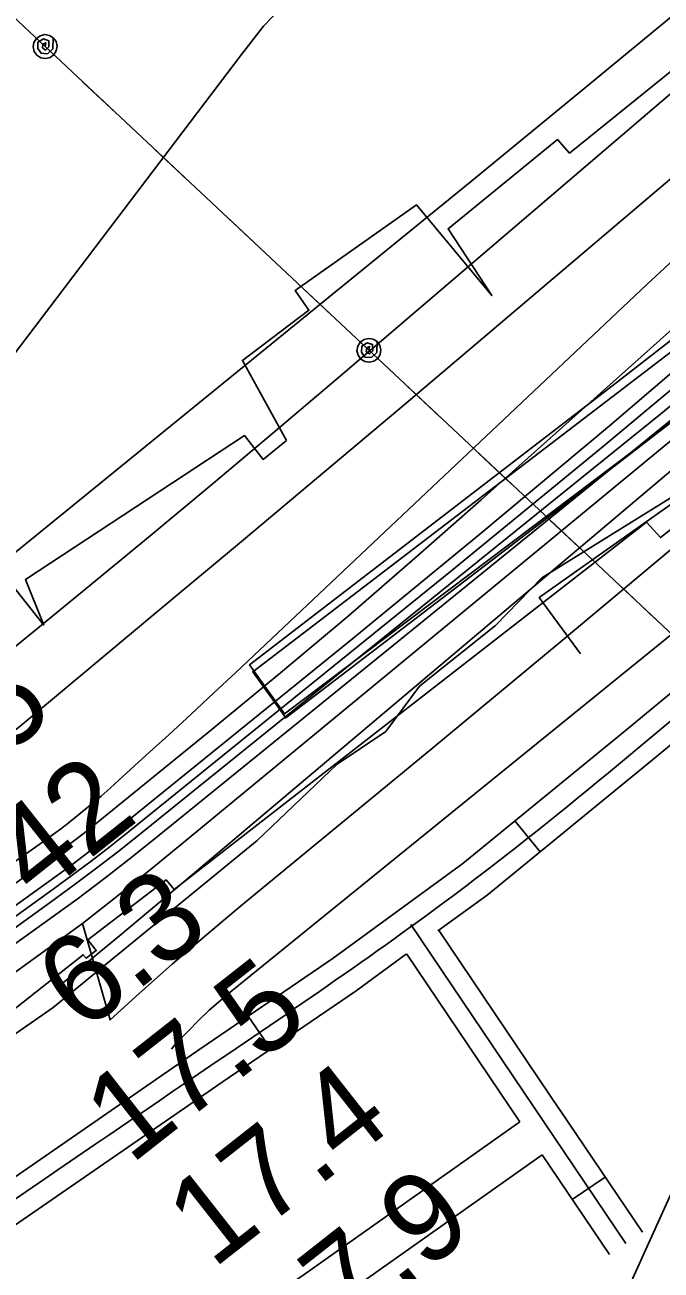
# Model space of a CAD drawing. Extents: x 3625074 to 3663148, y 511451 to 537151.
# Drawn here: x 3645581 to 3646060, y 521187 to 522124 of the extents above; entities that cross this region are included whole.
import ezdxf

# ---------------------------------------------------------------- set-up
doc = ezdxf.new("R2010")
doc.units = 0
for name, color, linetype in [('V-CHAN-DOCK', 7, 'Continuous'), ('V-LEVE-TOET', 7, 'Continuous'), ('V-RIVR-EDGE', 7, 'Continuous'), ('V-RIVR-RANG', 7, 'Continuous'), ('V-ROAD-CNTR', 7, 'Continuous'), ('V-RRAP-FSHR', 7, 'Continuous'), ('V-RRAP-RVMT', 7, 'Continuous'), ('V-TOPO-DPTH', 7, 'Continuous'), ('V-TOPO-MAJR', 7, 'Continuous'), ('V-TOPO-MINR', 7, 'Continuous'), ('V-TOPO-WATR', 7, 'Continuous'), ('V-UTIL-LINE', 7, 'Continuous')]:
    doc.layers.add(name, color=color, linetype=linetype)

msp = doc.modelspace()

# ---------------------------------------------------------------- linework, layer by layer
at = {"layer": 'V-CHAN-DOCK'}
msp.add_lwpolyline([(3647077.96, 522756.05), (3646494.93, 522231.96), (3646126.12, 521923.52), (3645752.62, 521637.55), (3645777.4, 521602.85), (3645987.62, 521763.73), (3646113.04, 521860.5), (3646144.11, 521817.9), (3646502.26, 522109.41), (3646582.43, 522257.46), (3646607.69, 522282.25), (3646709.59, 522172.98), (3646718.27, 522179.67), (3646642.33, 522262.11), (3646648.42, 522267.73), (3646654.37, 522261.27), (3646707.66, 522310.36), (3646678.61, 522341.89), (3646761.6, 522418.33), (3646806.4, 522369.7), (3646860.57, 522419.59), (3646817.55, 522466.3), (3646902.8, 522544.82)], dxfattribs=at)
at = {"layer": 'V-LEVE-TOET'}
msp.add_lwpolyline([(3646068.19, 521247.24), (3646026.38, 521154.84), (3645983.31, 521094.35), (3645844.66, 520999.75), (3645673.55, 520881.76), (3645536.38, 520786.62), (3645226.21, 520566.05), (3644923.09, 520354.77)], dxfattribs=at)
at = {"layer": 'V-RIVR-EDGE'}
msp.add_lwpolyline([(3644858.05, 520878.31), (3644968.08, 520945.88), (3645173.74, 521084.64), (3645302.43, 521176.18), (3645602.51, 521384.95), (3645755.9, 521510.64), (3645816.08, 521568.12), (3645852.76, 521592.64), (3645878.06, 521626.8), (3645935.2, 521672.28), (3645970.11, 521708.22), (3646075.93, 521773.99), (3646145.69, 521823.64), (3646116.97, 521862.74), (3645776.55, 521606.04), (3645750.23, 521642.72), (3646026.91, 521855.76), (3646319.23, 522083.16), (3646492.51, 522241.21), (3646750, 522464.5), (3646880.57, 522583.04)], dxfattribs=at)
at = {"layer": 'V-ROAD-CNTR'}
for p, q in [((3645968.72, 521502.17), (3645949.73, 521525.39)), ((3645766.08, 521353.73), (3645749.19, 521378.52)), ((3645992.89, 521240.58), (3646017.76, 521257.35))]:
    msp.add_line(p, q, dxfattribs=at)
for points in [[(3646202.23, 521733.05), (3646154.44, 521693.88), (3646032.61, 521593.13), (3645910.52, 521493.35), (3645812.98, 521421.98), (3645712.65, 521353.64), (3645559.67, 521247.79), (3645406.72, 521141.74), (3645302.19, 521066.22), (3645197.89, 520990.99), (3645080.09, 520911.17), (3644961.1, 520832.8), (3644862.35, 520768.83), (3644762.83, 520706.48), (3644752.66, 520700.73), (3644746.65, 520697.64)], [(3646209.85, 521700.51), (3646173.5, 521670.72), (3646051.66, 521569.96), (3645928.88, 521469.61), (3645891.9, 521442.55)], [(3646033.27, 521207.5), (3645871.52, 521447.45)], [(3645983.7, 521307.59), (3645892.8, 521442.72)], [(3645868.32, 521425.3), (3645830.29, 521397.48), (3645729.63, 521328.9), (3645576.75, 521223.12), (3645424.05, 521117.25), (3645319.75, 521041.9), (3645215.08, 520966.4), (3645096.76, 520886.22), (3644977.51, 520807.68), (3644918.88, 520769.71)], [(3645953.52, 521298.98), (3645868.47, 521425.13)], [(3646045.71, 521215.89), (3645983.6, 521308.03)], [(3645495.29, 520976.18), (3645636.38, 521076.89), (3645791.19, 521184.04), (3645953.52, 521298.98)], [(3645512.72, 520951.76), (3645653.63, 521052.35), (3645808.4, 521159.47), (3645970.29, 521274.1)], [(3646020.84, 521199.12), (3645970.29, 521274.1)]]:
    msp.add_lwpolyline(points, dxfattribs=at)
msp.add_spline([(3646385.44, 521861.38), (3646274.78, 521773.03), (3646163.97, 521682.3), (3645919.7, 521481.48), (3645721.14, 521341.27), (3645415.39, 521129.49), (3645206.49, 520978.7), (3644969.3, 520820.24), (3644770.51, 520693.59), (3644748.79, 520681.89)], degree=3, dxfattribs=at)
at = {"layer": 'V-RRAP-FSHR'}
msp.add_lwpolyline([(3645999.02, 521651.09), (3645968.08, 521693.34), (3646092.2, 521781.22), (3646140.44, 521816.06)], dxfattribs=at)
at = {"layer": 'V-RRAP-RVMT'}
for points in [[(3645778.05, 521811.6), (3645744.79, 521871.76), (3645794.83, 521909.61), (3645784.52, 521924.5), (3645875.64, 521988.83), (3645932.32, 521920.66), (3645899.45, 521970.94), (3645981.84, 522038.03), (3645990.85, 522027.65), (3646137.64, 522146.74), (3646162.19, 522118.42), (3646315.69, 522252.57), (3646307.62, 522263.78), (3646450.76, 522377.01)], [(3646566.5, 522236.25), (3646429.97, 522125.78), (3646446.91, 522104.74), (3646286.28, 521962.68), (3646270.34, 521979.94), (3646110.48, 521850.51), (3646127.66, 521829.57), (3646124.49, 521827.12), (3646142.29, 521802.96), (3646059.24, 521738.5), (3646048.7, 521750.21)], [(3646048.7, 521750.21), (3645693.48, 521473.65), (3645687.35, 521481.01), (3645628.52, 521435.89), (3645634.85, 521427.81), (3645627.27, 521422.06), (3645624.95, 521424.7), (3645481.09, 521311.15), (3645454.3, 521346.15), (3645455.47, 521347.06), (3645323.4, 521520.35), (3645397.29, 521586.01), (3645395.74, 521587.52), (3645557.37, 521720.5), (3645595.36, 521672.72), (3645581.65, 521707.11), (3645746.27, 521815.24), (3645760.37, 521797.4), (3645778.05, 521811.6)]]:
    msp.add_lwpolyline(points, dxfattribs=at)
at = {"layer": 'V-TOPO-DPTH'}
for points in [[(3647339.69, 522951.38), (3646608.99, 522302.38), (3646587.77, 522283.57), (3646566.54, 522264.78), (3646545.27, 522246.03), (3646523.98, 522227.3), (3646399.52, 522118), (3646315.54, 522045.16), (3646230.97, 521973.04), (3646145.5, 521901.98), (3646059.44, 521831.62), (3645668.58, 521516.15), (3645651.98, 521502.97), (3645635.25, 521489.97), (3645618.3, 521477.23), (3645601.23, 521464.68), (3644764.22, 520859.54)], [(3644764.22, 520859.54), (3645601.23, 521464.68), (3645618.3, 521477.23), (3645635.25, 521489.97), (3645651.98, 521502.97), (3645668.58, 521516.15), (3646059.44, 521831.62), (3646145.5, 521901.98), (3646230.97, 521973.04), (3646315.54, 522045.16), (3646399.52, 522118), (3646523.98, 522227.3), (3646545.27, 522246.03), (3646566.54, 522264.78), (3646587.77, 522283.57), (3646608.99, 522302.38), (3647339.69, 522951.38)], [(3644821.88, 520934.86), (3644923.65, 521001.72), (3645024.72, 521069.6), (3645124.75, 521139.02), (3645224.07, 521209.46), (3645603.76, 521483.12), (3645615.44, 521491.69), (3645627.02, 521500.38), (3645638.45, 521509.28), (3645649.78, 521518.3), (3645825.06, 521660.24), (3645923.42, 521740.98), (3646021.04, 521822.58), (3646117.58, 521905.46), (3646213.39, 521989.2), (3646494.37, 522238.11), (3646521.05, 522261.73), (3646547.73, 522285.35), (3646574.43, 522308.96), (3646601.13, 522332.56), (3646763.98, 522476.42)], [(3646763.98, 522476.42), (3646601.13, 522332.56), (3646574.43, 522308.96), (3646547.73, 522285.35), (3646521.05, 522261.73), (3646494.37, 522238.11), (3646213.39, 521989.2), (3646117.58, 521905.46), (3646021.04, 521822.58), (3645923.42, 521740.98), (3645825.06, 521660.24), (3645649.78, 521518.3), (3645638.45, 521509.28), (3645627.02, 521500.38), (3645615.44, 521491.69), (3645603.76, 521483.12), (3645224.07, 521209.46), (3645124.75, 521139.02), (3645024.72, 521069.6), (3644923.65, 521001.72), (3644821.88, 520934.86)], [(3646832.59, 522462.93), (3646750.1, 522390.1), (3646648.05, 522300.13), (3646616.52, 522272.37), (3646584.95, 522244.64), (3646553.33, 522216.97), (3646521.68, 522189.33), (3646520.78, 522188.54), (3646488.55, 522160.67), (3646456.16, 522132.98), (3646423.55, 522105.56), (3646390.78, 522078.32), (3645704.73, 521512.61), (3645678.17, 521490.91), (3645651.48, 521469.39), (3645624.6, 521448.11), (3644681.81, 520765.81)], [(3646832.59, 522462.93), (3646750.1, 522390.1), (3646648.05, 522300.13), (3646616.52, 522272.37), (3646584.95, 522244.64), (3646553.33, 522216.97), (3646521.68, 522189.33), (3646520.78, 522188.54), (3646488.55, 522160.67), (3646456.16, 522132.98), (3646423.55, 522105.56), (3646390.78, 522078.32), (3645704.73, 521512.61), (3645678.17, 521490.91), (3645651.48, 521469.39), (3645624.6, 521448.11)], [(3645624.6, 521448.11), (3645645.29, 521375.62), (3645667.16, 521395.52), (3645692.26, 521417.83), (3645717.74, 521439.71), (3645743.47, 521461.29), (3645886.55, 521579.19), (3645983.74, 521659.83), (3646080.56, 521740.9), (3646176.84, 521822.63), (3646272.75, 521904.78), (3646592.71, 522180.72), (3646606.83, 522192.98), (3646620.91, 522205.29), (3646634.9, 522217.7), (3646648.84, 522230.16), (3646893.45, 522450.21)], [(3645306.01, 521288.27), (3645384.77, 521343.08), (3645463.06, 521398.58), (3645606.32, 521501.53), (3645612.59, 521506.12), (3645618.8, 521510.79), (3645624.93, 521515.56), (3645631, 521520.4), (3645722.15, 521594.45), (3645773.45, 521636.73), (3645824.34, 521679.49), (3645874.61, 521722.98), (3645924.47, 521766.94), (3646511.67, 522292.19)], [(3646511.67, 522292.19), (3645924.47, 521766.94), (3645874.61, 521722.98), (3645824.34, 521679.49), (3645773.45, 521636.73), (3645722.15, 521594.45), (3645631, 521520.4), (3645624.93, 521515.56), (3645618.8, 521510.79), (3645612.59, 521506.12), (3645606.32, 521501.53), (3645463.06, 521398.58), (3645384.77, 521343.08), (3645306.01, 521288.27)], [(3644596.26, 520846.15), (3645548.55, 521477.78), (3645559.03, 521484.82), (3645569.45, 521491.92), (3645579.8, 521499.14), (3645590.1, 521506.44), (3645608.9, 521519.92), (3645611.43, 521521.82), (3645612.25, 521522.47), (3645624.61, 521532.52), (3645631.56, 521538.26), (3645638.44, 521544.08), (3645645.23, 521550.01), (3645651.95, 521556.03), (3645672.51, 521574.75), (3645689.42, 521590.23), (3645706.28, 521605.77), (3645723.05, 521621.39), (3645739.77, 521637.08), (3646049.11, 521928.91), (3646123.37, 521998.03), (3646198.23, 522066.46), (3646274.01, 522133.88)], [(3646274.01, 522133.88), (3646198.23, 522066.46), (3646123.37, 521998.03), (3646049.11, 521928.91), (3645739.77, 521637.08), (3645723.05, 521621.39), (3645706.28, 521605.77), (3645689.42, 521590.23), (3645672.51, 521574.75), (3645651.95, 521556.03), (3645645.23, 521550.01), (3645638.44, 521544.08), (3645631.56, 521538.26), (3645624.61, 521532.52), (3645612.25, 521522.47), (3645611.43, 521521.82), (3645608.9, 521519.92), (3645590.1, 521506.44), (3645579.8, 521499.14), (3645569.45, 521491.92), (3645559.03, 521484.82), (3645548.55, 521477.78), (3644596.26, 520846.15)]]:
    msp.add_lwpolyline(points, dxfattribs=at)
at = {"layer": 'V-TOPO-MAJR'}
msp.add_lwpolyline([(3644883.64, 521091.89), (3644988.39, 521166.06), (3645092.61, 521240.97), (3645196.48, 521316.37), (3645543.06, 521569.85), (3645552.21, 521576.68), (3645561.28, 521583.63), (3645570.22, 521590.74), (3645579.06, 521597.98), (3645684.26, 521685.66), (3645745.56, 521736.9), (3645806.78, 521788.25), (3645867.85, 521839.76), (3645928.84, 521891.39), (3646425.63, 522313.09), (3646452.95, 522336.12), (3646480.36, 522359.04), (3646507.92, 522381.79), (3646535.59, 522404.41), (3647111.04, 522871.97)], dxfattribs=at)
at = {"layer": 'V-TOPO-MINR'}
for points in [[(3644582.77, 520968.63), (3645480.34, 521651.95), (3645487.89, 521657.76), (3645495.4, 521663.62), (3645502.85, 521669.55), (3645510.27, 521675.52), (3645917.36, 522007.03), (3646001.6, 522076.11), (3646085.53, 522145.57), (3646169, 522215.58), (3646252.15, 522285.98), (3646390.26, 522403.7), (3646404.11, 522415.52), (3646417.96, 522427.36), (3646431.78, 522439.21), (3646445.6, 522451.07), (3647117.87, 523028.96)], [(3644595.24, 521097.76), (3645415.07, 521701.98), (3645431.19, 521714.11), (3645447.15, 521726.44), (3645462.86, 521739.09), (3645478.41, 521751.95), (3645744.23, 522102), (3645760.57, 522123.27), (3645779.49, 522142.89), (3646227.47, 522533.61), (3646253.63, 522556.06), (3646280.02, 522578.22), (3646306.77, 522599.95), (3646333.75, 522621.4), (3646754.89, 522950.68), (3646803.83, 522986.12), (3646854.28, 523019.03)], [(3645604.42, 521398.93), (3645610.57, 521404.14), (3645624.48, 521415.79), (3645638.43, 521427.38), (3645652.4, 521438.96), (3645666.34, 521450.57), (3645680.25, 521462.22), (3645694.13, 521473.91), (3646565.2, 522209.52), (3646570.07, 522213.65), (3646574.92, 522217.79), (3646579.76, 522221.95), (3646584.58, 522226.12), (3646589.4, 522230.31), (3646594.21, 522234.5), (3646599.01, 522238.71), (3646603.81, 522242.91), (3646617.18, 522254.65), (3646628.65, 522264.73), (3646640.12, 522274.82), (3646651.59, 522284.92), (3646663.05, 522295.03), (3647444.8, 522984.97)], [(3644764.22, 520859.54), (3645601.23, 521464.68), (3645618.3, 521477.23), (3645635.25, 521489.97), (3645651.98, 521502.97), (3645668.58, 521516.15), (3646059.44, 521831.62), (3646145.5, 521901.98), (3646230.97, 521973.04), (3646315.54, 522045.16), (3646399.52, 522118), (3646523.98, 522227.3), (3646545.27, 522246.03), (3646566.54, 522264.78), (3646587.77, 522283.57), (3646608.99, 522302.38), (3647339.69, 522951.38)], [(3644678.32, 520789.42), (3645620.56, 521466.43), (3645641.32, 521482.27), (3645661.86, 521498.4), (3645682.26, 521514.72), (3646222.14, 521952.8), (3646282.05, 522001.97), (3646341.58, 522051.57), (3646400.56, 522101.84), (3646459.17, 522152.54), (3646522.84, 522208.25), (3646549.31, 522231.46), (3646575.75, 522254.7), (3646602.15, 522277.98), (3646628.52, 522301.3), (3647118.2, 522735.2)], [(3644876.76, 520952.56), (3644938.09, 520995.06), (3644998.95, 521038.24), (3645602.49, 521473.9), (3645616.87, 521484.46), (3645631.13, 521495.18), (3645645.21, 521506.13), (3645659.18, 521517.23), (3645902.45, 521713.92), (3646013.64, 521804.99), (3646124.02, 521897.01), (3646233.21, 521990.45), (3646341.61, 522084.82), (3646525.1, 522246.66), (3646541.15, 522260.82), (3646557.2, 522274.99), (3646573.23, 522289.18), (3646589.26, 522303.37), (3647057.44, 522718.1)], [(3644821.88, 520934.86), (3644923.65, 521001.72), (3645024.72, 521069.6), (3645124.75, 521139.02), (3645224.07, 521209.46), (3645603.76, 521483.12), (3645615.44, 521491.69), (3645627.02, 521500.38), (3645638.45, 521509.28), (3645649.78, 521518.3), (3645825.06, 521660.24), (3645923.42, 521740.98), (3646021.04, 521822.58), (3646117.58, 521905.46), (3646213.39, 521989.2), (3646494.37, 522238.11), (3646521.05, 522261.73), (3646547.73, 522285.35), (3646574.43, 522308.96), (3646601.13, 522332.56), (3646763.98, 522476.42)], [(3645645.29, 521375.62), (3645667.16, 521395.52), (3645692.26, 521417.83), (3645717.74, 521439.71), (3645743.47, 521461.29), (3645886.55, 521579.19), (3645983.74, 521659.83), (3646080.56, 521740.9), (3646176.84, 521822.63), (3646272.75, 521904.78), (3646592.71, 522180.72), (3646606.83, 522192.98), (3646620.91, 522205.29), (3646634.9, 522217.7), (3646648.84, 522230.16), (3646893.45, 522450.21)], [(3645691.57, 521353.54), (3645693.99, 521356.88), (3645703.9, 521367.23), (3645711.78, 521375.17), (3645719.86, 521382.9), (3645728.22, 521390.31), (3645736.78, 521397.52), (3646344.81, 521890.45), (3646381.61, 521919.99), (3646418.6, 521949.28), (3646455.88, 521978.2), (3646493.35, 522006.88), (3646561.57, 522058.56), (3646565.2, 522060.95), (3646568.98, 522063), (3646573, 522064.54), (3646577.18, 522065.74), (3646581.43, 522066.8), (3646585.63, 522068.03), (3646589.75, 522069.51), (3646656.32, 522128.43), (3646929.92, 522411.85)], [(3644563.64, 520923.23), (3645053.71, 521268.88), (3645134.2, 521326.25), (3645214.31, 521384.14), (3645293.84, 521442.82), (3645372.99, 521502.03), (3645471.63, 521576.57), (3645501.04, 521599.07), (3645530.28, 521621.79), (3645559.25, 521644.84), (3645588.05, 521668.12), (3645627.24, 521700.18), (3645675.37, 521739.82), (3645723.33, 521779.66), (3645771.02, 521819.82), (3645818.54, 521860.18), (3646429.12, 522382.35)], [(3645306.01, 521288.27), (3645384.77, 521343.08), (3645463.06, 521398.58), (3645606.32, 521501.53), (3645612.59, 521506.12), (3645618.8, 521510.79), (3645624.93, 521515.56), (3645631, 521520.4), (3645722.15, 521594.45), (3645773.45, 521636.73), (3645824.34, 521679.49), (3645874.61, 521722.98), (3645924.47, 521766.94), (3646511.67, 522292.19)], [(3644596.26, 520846.15), (3645548.55, 521477.78), (3645559.03, 521484.82), (3645569.45, 521491.92), (3645579.8, 521499.14), (3645590.1, 521506.44), (3645608.9, 521519.92), (3645611.43, 521521.82), (3645612.25, 521522.47), (3645624.61, 521532.52), (3645631.56, 521538.26), (3645638.44, 521544.08), (3645645.23, 521550.01), (3645651.95, 521556.03), (3645672.51, 521574.75), (3645689.42, 521590.23), (3645706.28, 521605.77), (3645723.05, 521621.39), (3645739.77, 521637.08), (3646049.11, 521928.91), (3646123.37, 521998.03), (3646198.23, 522066.46), (3646274.01, 522133.88)]]:
    msp.add_lwpolyline(points, dxfattribs=at)
at = {"layer": 'V-TOPO-WATR'}
msp.add_lwpolyline([(3644681.81, 520765.81), (3645624.6, 521448.11), (3645651.48, 521469.39), (3645678.17, 521490.91), (3645704.73, 521512.61), (3646390.78, 522078.32), (3646423.55, 522105.56), (3646456.16, 522132.98), (3646488.55, 522160.67), (3646520.78, 522188.54), (3646521.68, 522189.33), (3646553.33, 522216.97), (3646584.95, 522244.64), (3646616.52, 522272.37), (3646648.05, 522300.13), (3646750.1, 522390.1), (3646832.59, 522462.93)], dxfattribs=at)
at = {"layer": 'V-UTIL-LINE'}
for points in [[(3646463.54, 521294.44), (3643690.19, 523896.23), (3642430.86, 525039.63), (3641157.78, 526208.74), (3640560.05, 526745.15), (3640328.95, 527487.85), (3640092.68, 528208.01), (3639626.15, 529640.19), (3639138.74, 531125.19), (3638954.79, 531677.02)], [(3645596.4, 522107.94), (3645596.83, 522110.78), (3645594.74, 522109.74), (3645594.41, 522107.02), (3645596.75, 522105.26), (3645599.19, 522107.63), (3645599.16, 522112.32), (3645595.11, 522113.67), (3645590.96, 522111.14), (3645590.88, 522106.56), (3645593.4, 522102.87), (3645598.21, 522102.57), (3645602.21, 522106.35), (3645602.56, 522114.5), (3645599.58, 522116.36), (3645596.12, 522116.93), (3645592.69, 522116.14), (3645589.84, 522114.09), (3645587.98, 522111.11), (3645587.41, 522107.65), (3645588.2, 522104.23), (3645590.24, 522101.37), (3645593.22, 522099.52), (3645596.69, 522098.94), (3645600.11, 522099.74), (3645602.97, 522101.78), (3645604.82, 522104.76), (3645605.4, 522108.22), (3645604.6, 522111.64), (3645602.56, 522114.5)], [(3645649.64, 522057.99), (3645624.85, 522081.25)], [(3645703.61, 522007.36), (3645678.81, 522030.62)], [(3645757.58, 521956.73), (3645732.78, 521979.99)], [(3645811.55, 521906.1), (3645786.75, 521929.36)], [(3645839.99, 521879.42), (3645840.41, 521882.26), (3645838.33, 521881.23), (3645838, 521878.5), (3645840.34, 521876.75), (3645842.78, 521879.11), (3645842.74, 521883.8), (3645838.7, 521885.16), (3645834.55, 521882.62), (3645834.46, 521878.05), (3645836.98, 521874.35), (3645841.8, 521874.05), (3645845.79, 521877.83), (3645846.15, 521885.98), (3645843.17, 521887.84), (3645839.7, 521888.41), (3645836.28, 521887.62), (3645833.43, 521885.58), (3645831.57, 521882.6), (3645830.99, 521879.13), (3645831.79, 521875.71), (3645833.83, 521872.86), (3645836.81, 521871), (3645840.28, 521870.42), (3645843.7, 521871.22), (3645846.55, 521873.26), (3645848.41, 521876.24), (3645848.98, 521879.71), (3645848.19, 521883.13), (3645846.15, 521885.98)], [(3645893.23, 521829.47), (3645868.43, 521852.74)], [(3645947.2, 521778.84), (3645922.4, 521802.11)], [(3646001.16, 521728.21), (3645976.37, 521751.48)], [(3646055.13, 521677.58), (3646030.34, 521700.85)]]:
    msp.add_lwpolyline(points, dxfattribs=at)

# ---------------------------------------------------------------- texts
at = {"layer": 'V-RIVR-RANG'}
for s, rotation, p in [('-55', 38.43847, (3645503.91, 521524.04)), ('-42', 38.43847, (3645566.71, 521446.22)), ('6.3', 38.15833, (3645624.78, 521365.18)), ('17.5', 38.15833, (3645660.62, 521266.16)), ('17.4', 38.15833, (3645722.59, 521187.68)), ('17.9', 38.15833, (3645784.36, 521109.04))]:
    msp.add_text(s, height=67, rotation=rotation, dxfattribs=at).set_placement(p)

doc.saveas('drawing.dxf')
